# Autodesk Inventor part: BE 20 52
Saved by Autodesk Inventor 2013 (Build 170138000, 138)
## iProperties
Created: 2012-12
Part Number: BE 20 52
Material: Générique
Document SubType Name: Modeling
Designer: jost thierry
Density: 1 g/cm^3
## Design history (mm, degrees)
node "BE 20 521"
node "BE 20 52"
node "Base1"
